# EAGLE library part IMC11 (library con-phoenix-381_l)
Invertierter Mini-Combicon 3.81mm horizontal 11-polig IMC 1,5/11-G-3,81 (ohne Gegenstecker)
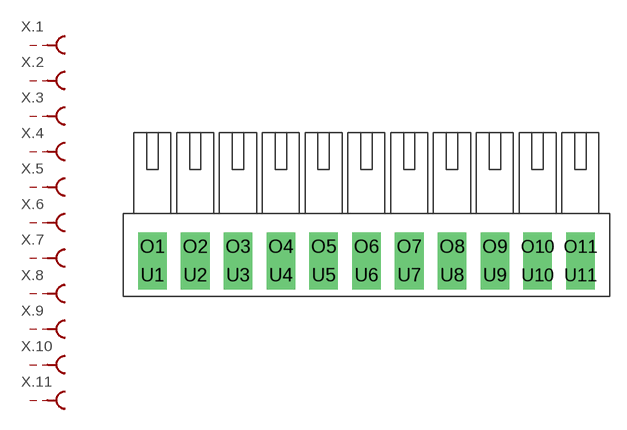
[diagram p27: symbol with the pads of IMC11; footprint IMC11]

Designator prefix X; gates .6=MCBU .5=MCBU .4=MCBU .3=MCBU .2=MCBU .1=MCBU .7=MCBU .8=MCBU .9=MCBU .10=MCBU .11=MCBU

## IMC11  [IMC11]
O1  .1:S  pas
O2  .2:S  pas
O3  .3:S  pas
O4  .4:S  pas
O5  .5:S  pas
O6  .6:S  pas
O7  .7:S  pas
O8  .8:S  pas
O9  .9:S  pas
O10  .10:S  pas
O11  .11:S  pas
U1  .1:SK  pas
U2  .2:SK  pas
U3  .3:SK  pas
U4  .4:SK  pas
U5  .5:SK  pas
U6  .6:SK  pas
U7  .7:SK  pas
U8  .8:SK  pas
U9  .9:SK  pas
U10  .10:SK  pas
U11  .11:SK  pas

## Footprint IMC11 (pad centres in mm)
Mini-Combicon 3.81mm horizontal 11-polig invertiert (ohne Gegenstecker)
drill 1.3 pad 2.54 square: O1 -19.05,1.27; O2 -15.24,1.27; O3 -11.43,1.27; O4 -7.62,1.27; O5 -3.81,1.27; O6 0,1.27; O7 3.81,1.27; O8 7.62,1.27; O9 11.43,1.27; O10 15.24,1.27; O11 19.05,1.27; U1 -19.05,-1.27; U2 -15.24,-1.27; U3 -11.43,-1.27; U4 -7.62,-1.27; U5 -3.81,-1.27; U6 0,-1.27; U7 3.81,-1.27; U8 7.62,-1.27; U9 11.43,-1.27; U10 15.24,-1.27; U11 19.05,-1.27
